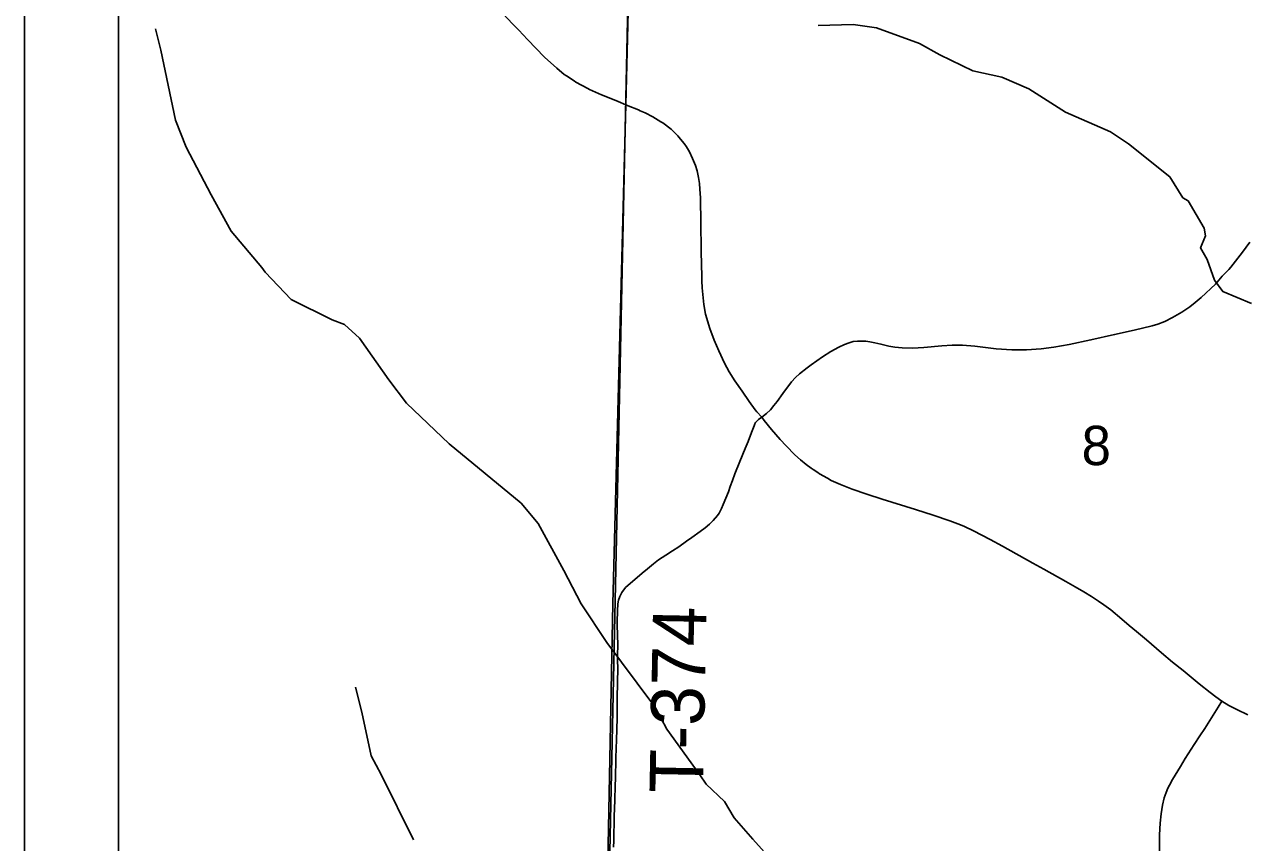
# Model space of a CAD drawing. Extents: x 0 to 34, y 0 to 22.
# Drawn here: x 2.5 to 3.798, y 14.697 to 15.568 of the extents above; entities that cross this region are included whole.
import ezdxf

# ---------------------------------------------------------------- set-up
doc = ezdxf.new("R2010")
doc.units = 0
for name, color, linetype in [('GM_X_Corporation', 7, 'Continuous'), ('GM_X_Minor_River', 7, 'Continuous'), ('GM_X_Section_Text', 7, 'Continuous'), ('GM_X_State_Route', 7, 'Continuous'), ('GM_X_Township_Road', 7, 'Continuous'), ('GM_X_Township_Road_Text', 7, 'Continuous'), ('SH_Data', 7, 'Continuous')]:
    doc.layers.add(name, color=color, linetype=linetype)

msp = doc.modelspace()

# ---------------------------------------------------------------- linework, layer by layer
at = {"layer": 'GM_X_Corporation'}
for points in [[(2.6, 16.6918), (2.6, 13.6), (9.4, 13.6), (9.4, 16.4853), (9.09, 16.4927), (8.0963, 16.5226), (6.2194, 16.578), (6.0834, 16.5816), (5.4202, 16.5982), (4.6351, 16.6229), (4.5473, 16.6256), (4.1867, 16.6352), (4.1011, 16.6362), (4.0515, 16.6368), (3.1684, 16.6682), (3.1555, 16.6686)], [(2.6, 16.6918), (2.6, 13.6417), (3.0575, 13.6324), (3.1025, 13.6315), (3.1033, 13.7653), (3.1089, 14.0542), (3.109, 14.0614), (3.1121, 14.2169), (3.1127, 14.2486), (3.1134, 14.2853), (3.1142, 14.3277), (3.1263, 14.9513), (3.1401, 15.483), (3.148, 15.8071), (3.1555, 16.6686)], [(2.6, 15.673), (2.6, 14.6526), (3.1218, 14.6372), (3.1435, 15.6571)], [(4.1616, 15.6255), (4.1372, 14.6117), (3.1218, 14.6372), (3.1435, 15.6571)]]:
    msp.add_lwpolyline(points, close=True, dxfattribs=at)
msp.add_lwpolyline([(3.1555, 16.6686), (3.148, 15.8071), (3.1401, 15.483), (3.1263, 14.9513), (3.1142, 14.3277), (3.1134, 14.2853), (3.1127, 14.2486), (3.1121, 14.2169), (3.109, 14.0614), (3.1089, 14.0542), (3.1033, 13.7653), (3.1025, 13.6315), (3.2812, 13.6297), (3.3525, 13.6282), (4.3222, 13.6092), (4.5781, 13.6), (9.4, 13.6)], dxfattribs=at)
at = {"layer": 'GM_X_Minor_River'}
for points in [[(3.8056, 15.2709), (3.7751, 15.2838), (3.7665, 15.2958), (3.7586, 15.318), (3.7516, 15.3304), (3.7567, 15.343), (3.7555, 15.3513), (3.7384, 15.3803), (3.7326, 15.3836), (3.719, 15.4058), (3.6749, 15.4411), (3.6706, 15.4437), (3.6557, 15.4537), (3.608, 15.4746), (3.5689, 15.4995), (3.5402, 15.5119), (3.5094, 15.5187), (3.4742, 15.5356), (3.4524, 15.5478), (3.4066, 15.5645), (3.3819, 15.568), (3.3448, 15.567)], [(3.306, 14.6665), (3.2752, 14.701), (3.2551, 14.7234), (3.245, 14.7411), (3.2254, 14.7594), (3.2188, 14.7695), (3.1835, 14.8179), (3.1714, 14.8408), (3.1675, 14.8461), (3.1199, 14.9102), (3.0924, 14.9515), (3.074, 14.9869), (3.0467, 15.0369), (3.0286, 15.0586), (2.9521, 15.1215), (2.9067, 15.1648), (2.8877, 15.1899), (2.8567, 15.2342), (2.8406, 15.2487), (2.8276, 15.2538), (2.784, 15.2752), (2.7563, 15.3043), (2.7528, 15.3092), (2.72, 15.3481), (2.6989, 15.3868), (2.672, 15.4376), (2.6609, 15.4662), (2.645, 15.5406), (2.6394, 15.5633)], [(2.9139, 14.7002), (2.8795, 14.7698), (2.869, 14.7897), (2.8592, 14.8362), (2.8523, 14.8626)]]:
    msp.add_lwpolyline(points, dxfattribs=at)
at = {"layer": 'GM_X_State_Route'}
for points in [[(3.0036, 15.5859), (3.0198, 15.5683), (3.026, 15.5619), (3.0353, 15.5522), (3.0534, 15.5332), (3.0666, 15.5215), (3.0745, 15.5149), (3.0767, 15.5133), (3.085, 15.508), (3.0869, 15.5068), (3.0996, 15.4998), (3.1012, 15.4989), (3.114, 15.4933), (3.1293, 15.487), (3.1425, 15.4814)], [(3.1425, 15.4814), (3.1533, 15.4772), (3.1553, 15.4763), (3.1604, 15.4739), (3.1687, 15.4697), (3.1774, 15.4646), (3.1794, 15.4632), (3.1881, 15.4566), (3.1954, 15.4494), (3.1983, 15.4461), (3.2022, 15.4412), (3.2044, 15.4377), (3.2077, 15.4325), (3.2111, 15.4255), (3.214, 15.418), (3.2158, 15.4123), (3.2174, 15.4051), (3.2183, 15.3988), (3.2188, 15.3928), (3.2193, 15.3836), (3.2196, 15.3722), (3.2197, 15.3677), (3.2198, 15.3587), (3.2203, 15.3259), (3.2207, 15.2998), (3.2208, 15.2952), (3.2212, 15.2879), (3.2221, 15.277), (3.2231, 15.27), (3.2249, 15.2598), (3.2293, 15.2443), (3.234, 15.2319), (3.2389, 15.2208), (3.245, 15.2075), (3.2501, 15.1984), (3.2561, 15.1887), (3.2637, 15.1776), (3.2713, 15.1667), (3.2777, 15.158), (3.2795, 15.1557), (3.2846, 15.1499), (3.2873, 15.1465), (3.2949, 15.1371), (3.3042, 15.1264), (3.3106, 15.1194), (3.3197, 15.11), (3.3257, 15.1047), (3.332, 15.0997), (3.3372, 15.0958), (3.3393, 15.0943), (3.3444, 15.091), (3.3461, 15.0898), (3.3544, 15.085), (3.3586, 15.0828), (3.3683, 15.0783), (3.381, 15.0734), (3.3965, 15.0681), (3.4129, 15.0628), (3.4483, 15.0518), (3.4671, 15.0457), (3.4847, 15.0398), (3.4961, 15.0354), (3.5002, 15.0336), (3.5101, 15.029), (3.5277, 15.0198), (3.5408, 15.0127), (3.5732, 14.9947), (3.5847, 14.9883), (3.6083, 14.9752), (3.6182, 14.9695), (3.6273, 14.9642), (3.6356, 14.959), (3.643, 14.9542), (3.6488, 14.9502), (3.656, 14.9448), (3.6678, 14.9352), (3.6757, 14.9284), (3.6833, 14.9218), (3.6939, 14.913), (3.71, 14.8993), (3.7218, 14.8894), (3.7329, 14.8804), (3.75, 14.8661), (3.7618, 14.8569), (3.7677, 14.8522), (3.7742, 14.8478), (3.7816, 14.8433), (3.7903, 14.8388), (3.8019, 14.8332)]]:
    msp.add_lwpolyline(points, dxfattribs=at)
at = {"layer": 'GM_X_Township_Road'}
for points in [[(3.2846, 15.1499), (3.2897, 15.1541), (3.2938, 15.1579), (3.2976, 15.1624), (3.3011, 15.1668), (3.307, 15.1751), (3.3164, 15.1878), (3.3205, 15.1922), (3.3248, 15.1963), (3.3328, 15.2025), (3.3371, 15.2057), (3.3493, 15.2141), (3.3582, 15.2199), (3.3665, 15.2246), (3.3726, 15.2274), (3.3775, 15.2293), (3.3818, 15.2305), (3.3865, 15.2311), (3.3954, 15.2308), (3.3995, 15.2302), (3.4049, 15.2292), (3.4114, 15.2278), (3.4197, 15.2257), (3.4263, 15.2246), (3.434, 15.2238), (3.445, 15.2236), (3.4571, 15.2243), (3.4764, 15.2261), (3.4874, 15.2268), (3.4982, 15.2266), (3.5112, 15.2256), (3.5339, 15.2229), (3.5506, 15.2216), (3.5664, 15.2218), (3.5818, 15.2228), (3.5955, 15.2247), (3.6116, 15.2275), (3.6348, 15.2323), (3.66, 15.238), (3.681, 15.2428), (3.6999, 15.2472), (3.7062, 15.249), (3.7134, 15.252), (3.7217, 15.2561), (3.7318, 15.2619), (3.74, 15.2676), (3.7459, 15.272), (3.7521, 15.2773), (3.7673, 15.2915), (3.7747, 15.3), (3.7771, 15.3027), (3.7815, 15.3073), (3.7837, 15.3098), (3.7963, 15.3258), (3.8041, 15.3364)], [(3.1316, 14.9514), (3.1323, 14.9552), (3.1337, 14.959), (3.1358, 14.9635), (3.1398, 14.9687), (3.1473, 14.9756), (3.1522, 14.9795), (3.1575, 14.9841), (3.1629, 14.9885), (3.1693, 14.9939), (3.1748, 14.9981), (3.1824, 15.0032), (3.1897, 15.0077), (3.1964, 15.0122), (3.2047, 15.0181), (3.2103, 15.0221), (3.219, 15.0283), (3.2244, 15.0324), (3.2289, 15.0362), (3.2329, 15.0402), (3.2374, 15.0455), (3.2392, 15.048), (3.2418, 15.0529), (3.2437, 15.0572), (3.2491, 15.0707), (3.2511, 15.0763), (3.2534, 15.0826), (3.2561, 15.0896), (3.2612, 15.1028), (3.267, 15.1167), (3.2701, 15.124), (3.2736, 15.1336), (3.2764, 15.141), (3.2772, 15.1428), (3.2781, 15.1442), (3.2795, 15.1459), (3.2813, 15.1475), (3.2846, 15.1499)], [(3.1269, 14.6922), (3.1272, 14.699), (3.1276, 14.7254), (3.1283, 14.742), (3.1286, 14.7585), (3.129, 14.7649), (3.1293, 14.7871), (3.1297, 14.7976), (3.1299, 14.8062), (3.1306, 14.8297), (3.1307, 14.8479), (3.1311, 14.8707), (3.1313, 14.8796), (3.1311, 14.8943), (3.1314, 14.91), (3.1311, 14.9159), (3.1307, 14.931), (3.131, 14.945), (3.1314, 14.9504), (3.1316, 14.9514)], [(3.7079, 14.6695), (3.708, 14.7055), (3.7086, 14.718), (3.7095, 14.7279), (3.711, 14.7371), (3.7128, 14.7447), (3.7148, 14.7505), (3.7167, 14.755), (3.7185, 14.7585), (3.7218, 14.7644), (3.7302, 14.7782), (3.7353, 14.7866), (3.7449, 14.8017), (3.7509, 14.8107), (3.7561, 14.8188), (3.7702, 14.8414), (3.7742, 14.8478)]]:
    msp.add_lwpolyline(points, dxfattribs=at)
at = {"layer": 'SH_Data'}
for points in [[(2.5, 20.5), (9.5, 20.5), (9.5, 13.5), (2.5, 13.5)], [(2.6, 20.4), (9.4, 20.4), (9.4, 13.6), (2.6, 13.6)]]:
    msp.add_lwpolyline(points, close=True, dxfattribs=at)

# ---------------------------------------------------------------- texts
at = {"layer": 'GM_X_Section_Text'}
msp.add_text('8', height=0.0419, rotation=0, dxfattribs=at).set_placement((3.625, 15.099))
at = {"layer": 'GM_X_Township_Road_Text'}
msp.add_text('T-374', height=0.05682, rotation=88.8762, dxfattribs=at).set_placement((3.2219, 14.7495))

doc.saveas('drawing.dxf')
